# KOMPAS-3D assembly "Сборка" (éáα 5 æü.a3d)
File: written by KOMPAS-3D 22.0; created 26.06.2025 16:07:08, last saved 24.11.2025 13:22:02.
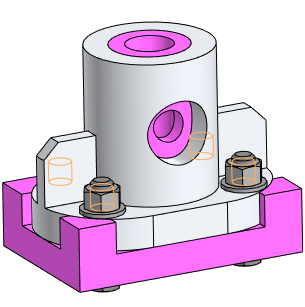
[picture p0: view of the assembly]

Document properties: Автор: Helen; Полное имя файла: C:\Для ноута\Инженерная графика\ППЭ 2025-2026\Варианты 1-38\Вариант 5 СБ\Вар 5 СБ\Вар 5 СБ.a3d

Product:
- Component [detail]: Основание  | designation Вариант 5  | qty 1  | Масса: 3.438966; source file: Основание вар 5.m3d
- Component [detail]: Nodes  | qty 1  | Масса: 3.667663; source file: Корпус вар 5.m3d
- Component [detail]: Болт М14x60 ГОСТ 15591-70  | qty 4  | Масса: 0.091885; source file: Болт М14x60 ГОСТ 15591-70.m3d
- Component [detail]: Сборка  | qty 4  | Масса: 0.008612; source file: Шайба 14.m3d
- Component [detail]: Сборка  | qty 4  | Масса: 0.02533; source file: Гайка М14.m3d
- Part/product: Сборка
    Масса: 7.609936

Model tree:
1. Массив по концентрической сетке:1  (with: Элемент выдавливания:4)  (2 pattern instances)
     Шаг 2 = 60
2. Массив по концентрической сетке:2  (with: Операция без истории:1, Элемент выдавливания:3, Элемент выдавливания:1)  (labels: Фаска:3; Фаска:3)  (2 pattern instances)
     Шаг 2 = 60

Referenced files in C:\Для ноута\Инженерная графика\ППЭ 2025-2026\Варианты 1-38\Вариант 5 СБ\Вар 5 СБ\: Основание вар 5.m3d, Корпус вар 5.m3d, Болт М14x60 ГОСТ 15591-70.m3d, Шайба 14.m3d, Гайка М14.m3d
Referenced files in D:\MY\WORK\MPEI\ППЭ_2025-2026\Варианты\Вар 5 СБ\: Болт М14x60 ГОСТ 15591-70.m3d, Гайка М14.m3d, Шайба 14.m3d
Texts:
  Вариант 5 Основание
  Болт М14x60 ГОСТ 15591-70 (1)
  Сборка (1)
  Болт М14x60 ГОСТ 15591-70 (3)
  Сборка (3)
